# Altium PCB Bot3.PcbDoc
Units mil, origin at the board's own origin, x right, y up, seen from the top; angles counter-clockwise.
Board outline 1654.8 x 2956.3 mil, 2 copper layers (Top1, Bottom2), stack 42.17 mil thick; 83 components, 55 nets, 452 pads, 351 vias.
Unrouted connection lines stored in the file: 11.
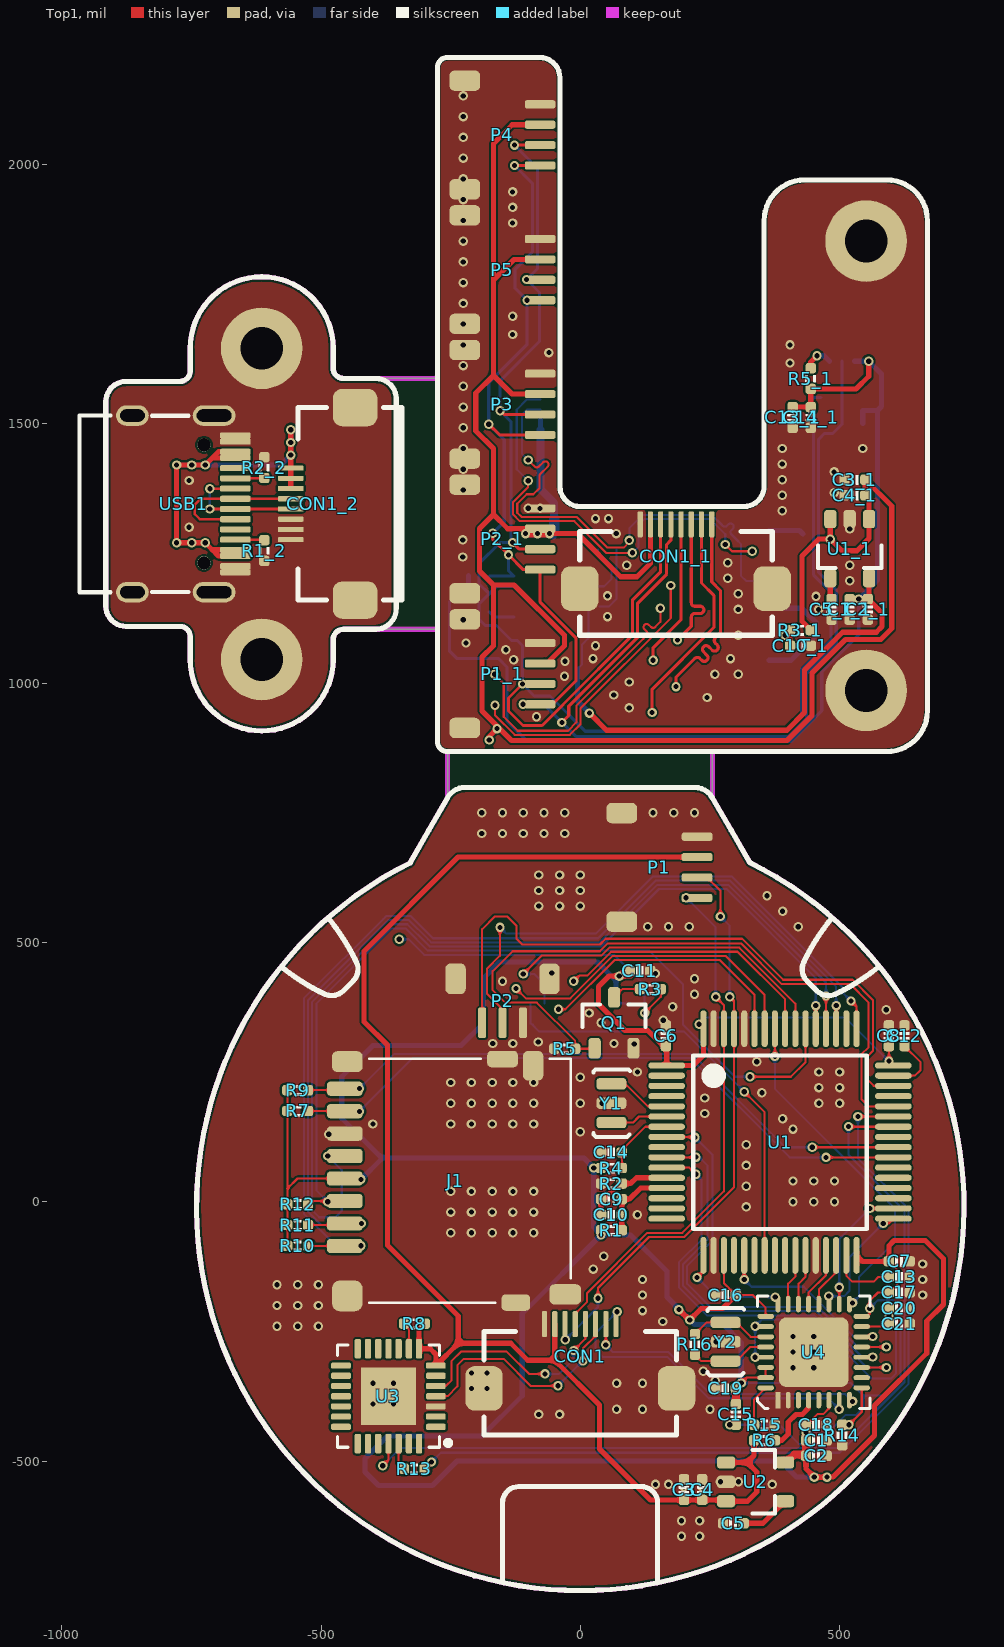
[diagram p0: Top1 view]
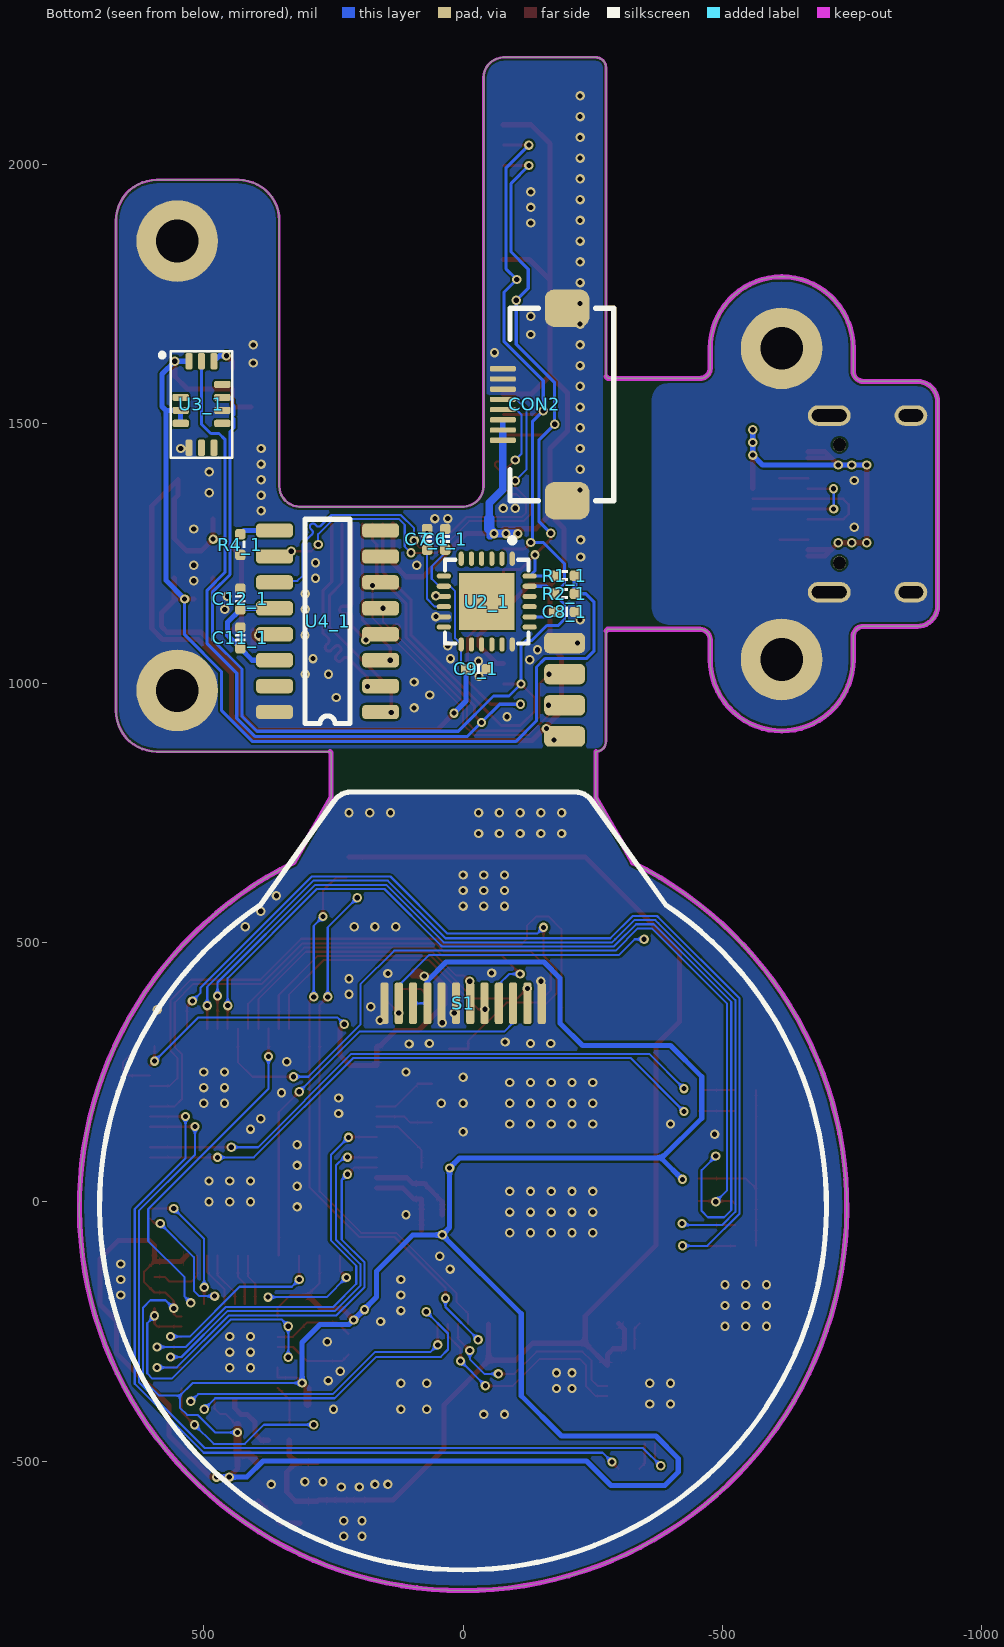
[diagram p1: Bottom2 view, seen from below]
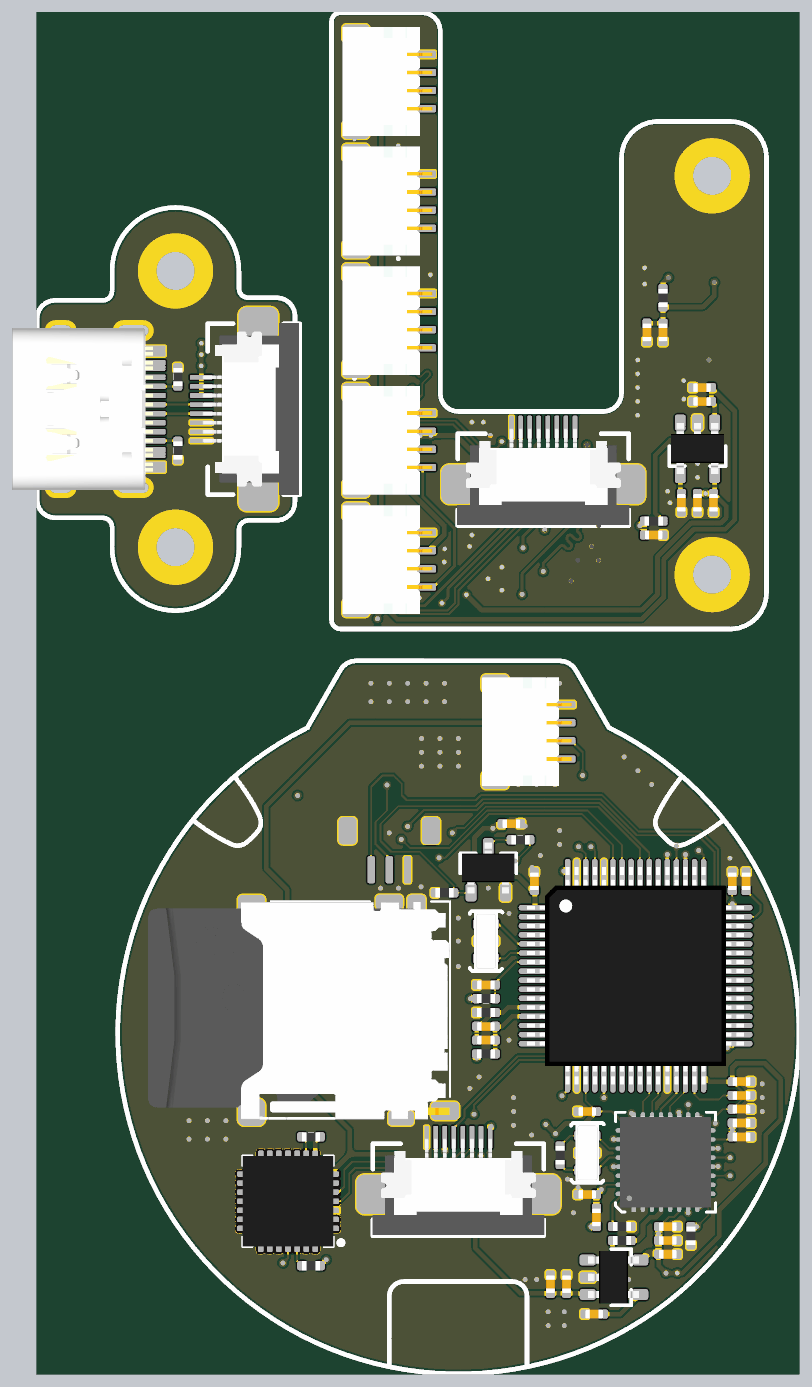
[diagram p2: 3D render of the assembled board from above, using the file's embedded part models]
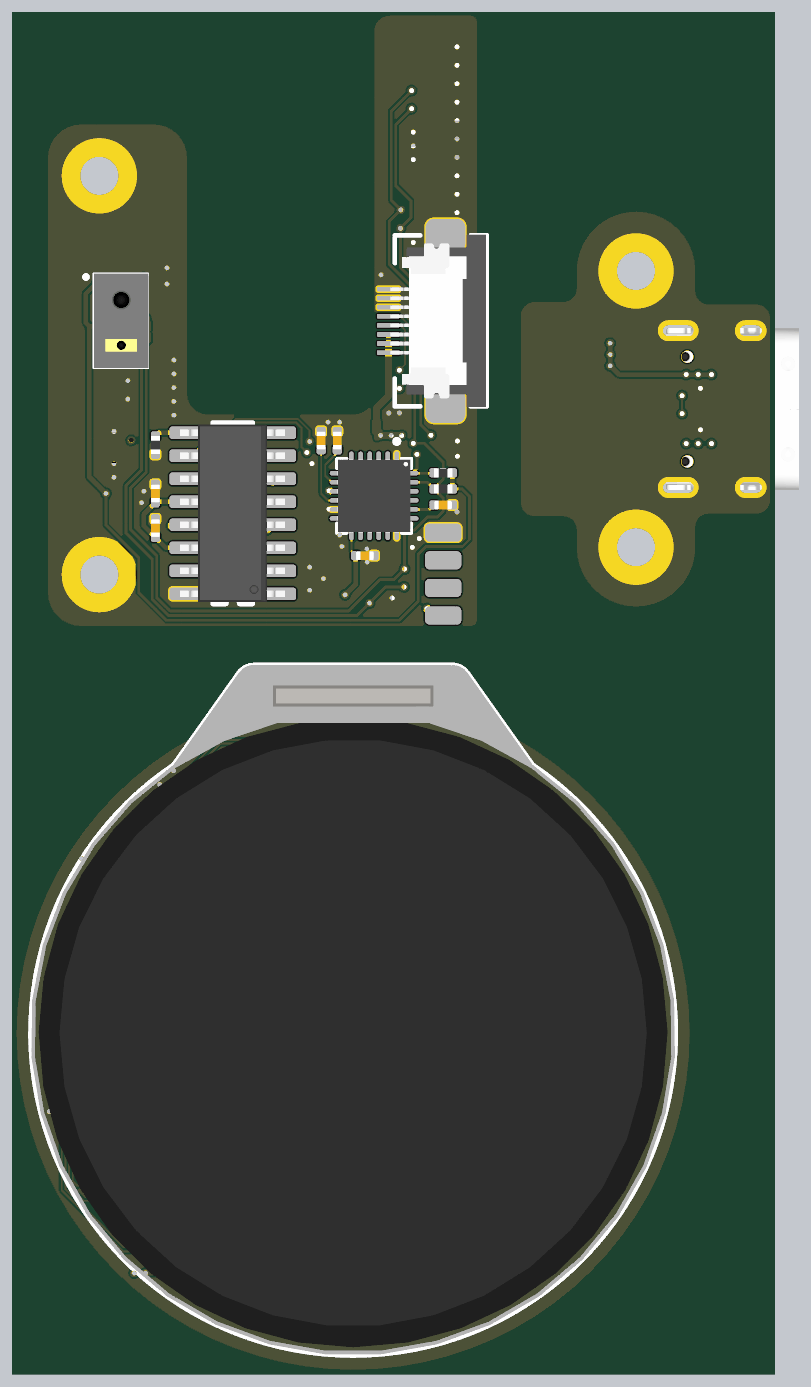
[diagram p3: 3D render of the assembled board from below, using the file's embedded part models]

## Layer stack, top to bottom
Top Solder: solder mask 0.4, Solder Resist, Dk 3.5
Top1: signal copper 1.4
Dielectric 1: prepreg 39.3701, PP-006, Dk 4.1
Bottom2: signal copper 1.4
Bottom Solder: solder mask 0.4, Solder Resist, Dk 3.5

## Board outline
-752.13,1045.51 -752.13,1089.61 ccw(c-771.81,1089.61) -771.81,1109.29 -875.58,1109.29 cw(c-875.58,1148.66) -914.95,1148.66 -914.95,1542.36 cw(c-875.58,1542.36) -875.58,1581.73 -771.81,1581.73 ccw(c-771.81,1601.42) -752.13,1601.42 -752.13,1645.51 cw(c-614.33,1645.51) -476.54,1645.51 -476.54,1607.05 ccw(c-456.85,1607.05) -456.85,1587.36 -279.64,1587.36 -275.59,1591.41 -275.59,2186.75 cw(c-255.91,2186.75) -255.91,2206.43 -78.74,2206.43 cw(c-78.74,2167.06) -39.37,2167.06 -39.37,1379.66 ccw(c0,1379.66) 0,1340.29 314.96,1340.29 ccw(c314.96,1379.66) 354.33,1379.66 354.33,1891.47 cw(c433.07,1891.47) 433.07,1970.21 590.55,1970.21 cw(c590.55,1891.47) 669.29,1891.47 669.29,946.59 cw(c590.55,946.59) 590.55,867.85 256.85,867.85 254.64,865.64 254.64,779.01 290.88,716.22 326.65,654.22 326.51,653.93 cw(c0,-10) -327.21,653.58 -327.58,654.33 -292.13,716.15 -256.03,779.09 -256.03,867.72 -255.91,867.85 cw(c-255.91,887.54) -275.59,887.54 -275.59,1100.59 -278.66,1103.66 -456.85,1103.66 ccw(c-456.85,1083.98) -476.54,1083.98 -476.54,1045.51 cw(c-614.33,1045.51)

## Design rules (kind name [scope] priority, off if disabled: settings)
Clearance Clearance_Logo [InNetClass('Logo')] p1: gap=8 ignorepadtopadclearanceinfootprint=FALSE
Clearance [All] p2: gap=4 ignorepadtopadclearanceinfootprint=FALSE except(0: Arc-Hole Track-Hole SMDPad-Hole THPad-Hole Via-Hole Fill-Hole Poly-Hole Region-Hole Text-Hole)
ComponentClearance [All] p1: gap=0 collisioncheckmode=3 verticalgap=0 showdistances=FALSE
DiffPairsRouting [All] p1: maxlimit=9 minlimit=9 mostfreqgap=9 toplayer_minwidth=15 toplayer_maxwidth=15 toplayer_prefwidth=15 bottomlayer_minwidth=15 bottomlayer_maxwidth=15 bottomlayer_prefwidth=15 maxuncoupledlength=500
FanoutControl Fanout_BGA [All] p1: bgadir=Out bgaviamode=Centered fanoutstyle=Auto fanoutdirection=Alternating viagrid=1 // Fanout_BGA (Default Rule)
HoleSize [All] p1: absolutevalues=TRUE maxlimit=10000 minlimit=8 maxpercent=80.000 minpercent=20.000
MinimumSolderMaskSliver [All] p1 off: minsoldermaskwidth=2
PlaneClearance [All] p1: clearance=8
PlaneConnect [All] p1: planeconnectstyle=Direct reliefexpansion=20 reliefentries=4 reliefconductorwidth=10 reliefairgap=10
PolygonConnect [All] p1: connectstyle=Direct reliefconductorwidth=10 reliefentries=4 polygonreliefangle="90 Angle" airgapwidth=10
RoutingVias [All] p1: holewidth=8 width=16 viastyle="Through Hole" minholewidth=6 minwidth=12 maxholewidth=28 maxwidth=50
SilkToSilkClearance [All] p1: silktosilkclearance=0
SilkToSolderMaskClearance [IsPad] p1: minsilkscreentomaskgap=0 clearancetoexposedcopper=TRUE
SolderMaskExpansion [All] p1: expansion=3 istentingtop=FALSE
Width Logo [InNetClass('Logo')] p1: maxlimit=100 minlimit=0.1 preferedwidth=10
Width GND [(InNet('AGND') OR InNet('GND'))] p2: maxlimit=50 minlimit=4 preferedwidth=10
Width VCC [(InNet('VDD_SYS_3.3V') OR InNet('VDD_AV_3.3V') OR InNet('VDD_5V') OR InNet('VDD1V2-SYS') OR InNet('VDD1V1-EPHY') OR InNet('VDD-CPUX') OR InNet('VDD-CPUS') OR InNet('VDD-CPUFB') OR InNet('VCC-DRAM'))] p3: maxlimit=50 minlimit=4 preferedwidth=10
Width [All] p4: maxlimit=10000 minlimit=4 preferedwidth=4
21 further rules are at their usual default settings.

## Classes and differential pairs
component class Main: C1 C2 C3 C4 C5 C6 C7 C8 C9 C10 C11 C12 C13 C14 C15 C16 C17 C18 C19 C20 C21 CON1 J1 P1 P2 Q1 R1 R2 R3 R4 R5 R6 R7 R8 R9 R10 R11 R12 R13 R14 R15 R16 S1 U1 U2 U3 U4 Y1 Y2

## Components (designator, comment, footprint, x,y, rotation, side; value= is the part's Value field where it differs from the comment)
C1 "0.1uF" CAP_0402 455,-460 r180 top value=0.1u
C1_1 "0.1uF" CAP_0402 519.41,1142.14 r90 top value=0.1u (schematic designator C1)
C2 "10uF" CAP_0402 455,-490 r180 top value=0.1u
C2_1 "10uF" CAP_0402 554.41,1142.14 r90 top value=0.1u (schematic designator C2)
C3 "10uF" CAP_0402 200,-555 r270 top value=0.1u
C3_1 "10uF" CAP_0402 529.41,1392.14 r0 top value=0.1u (schematic designator C3)
C4 "0.1uF" CAP_0402 235,-555 r270 top value=0.1u
C4_1 "0.1uF" CAP_0402 529.41,1362.14 r0 top value=0.1u (schematic designator C4)
C5 "10nF" CAP_0402 295,-620 r0 top value=0.1u
C5_1 "10nF" CAP_0402 484.41,1142.14 r90 top value=0.1u (schematic designator C5)
C6 "0.1uF" CAP_0402 165,320 r270 top value=0.1u
C6_1 "10nF" CAP_0402 34.41,1277.14 r90 bottom value=0.1u (schematic designator C6)
C7 "0.1uF" CAP_0402 615,-115 r180 top value=0.1u
C7_1 "0.1uF" CAP_0402 69.41,1277.14 r90 bottom value=0.1u (schematic designator C7)
C8 "0.1uF" CAP_0402 595,320 r270 top value=0.1u
C8_1 "2.2nF" CAP_0402 -195.59,1137.14 r0 bottom value=0.1u (schematic designator C8)
C9 "0.1uF" CAP_0402 60,5 r0 top value=0.1u
C9_1 "0.1uF" CAP_0402 -25.59,1027.14 r0 bottom value=0.1u (schematic designator C9)
C10 "10uF" CAP_0402 60,-25 r0 top value=0.1u
C10_1 "10uF" CAP_0402 424.41,1072.14 r180 top value=0.1u (schematic designator C10)
C11 "0.1uF" CAP_0402 115,445 r180 top value=0.1u
C11_1 "10uF" CAP_0402 429.41,1087.14 r90 bottom value=0.1u (schematic designator C11)
C12 "10uF" CAP_0402 625,320 r270 top value=0.1u
C12_1 "0.1uF" CAP_0402 429.41,1162.14 r90 bottom value=0.1u (schematic designator C12)
C13 "10uF" CAP_0402 615,-145 r180 top value=0.1u
C13_1 "10uF" CAP_0402 409.41,1512.14 r270 top value=0.1u (schematic designator C13)
C14 "0.1uF" CAP_0402 60,95 r0 top value=0.1u
C14_1 "0.1uF" CAP_0402 444.41,1512.14 r270 top value=0.1u (schematic designator C14)
C15 "10nF" CAP_0402 300,-410 r270 top value=0.1u
C16 "0.1uF" CAP_0402 280,-180 r180 top value=0.1u
C17 "0.1uF" CAP_0402 615,-175 r0 top value=0.1u
C18 "0.1uF" CAP_0402 455,-430 r0 top value=0.1u
C19 "0.1uF" CAP_0402 280,-360 r180 top value=0.1u
C20 "10uF" CAP_0402 615,-205 r0 top value=0.1u
C21 "0.1uF" CAP_0402 615,-235 r0 top value=0.1u
CON1 "FFC_0.5_8" FFC_0.5_8 0,-325 r0 top
CON1_1 "FFC_0.5_8" FFC_0.5_8 184.41,1217.14 r0 top (schematic designator CON1)
CON1_2 "FFC_0.5_8" FFC_0.5_8 -469.33,1345.51 r90 top locked (schematic designator CON1)
CON2 "FFC_0.5_8" FFC_0.5_8 -165.59,1537.14 r90 bottom locked
J1 "TF-Socket" "TF-Card-Amphenol with TF" -454.13,44.68 r270 top locked
P1 "SH1.0-4P" SH1.0-4P 225,644.69 r270 top locked
P1_1 "SH1.0-4P" SH1.0-4P -77.59,1018.17 r270 top locked (schematic designator P1)
P2 "SH1.0-3P-STAND" SH1.0-3P-STAND -150,345 r180 top locked
P2_1 "SH1.0-4P" SH1.0-4P -77.59,1277.85 r270 top locked (schematic designator P2)
P3 "SH1.0-4P" SH1.0-4P -77.59,1537.54 r270 top locked
P4 "SH1.0-4P" SH1.0-4P -77.59,2056.91 r270 top locked
P5 "SH1.0-4P" SH1.0-4P -77.59,1797.22 r270 top locked
Q1 "AO3400A" SOT23-3 65,345 r90 top locked
R1 "0R" RES_0402 60,-55 r180 top value=22R
R1_1 "10K" RES_0402 -195.59,1207.14 r180 bottom value=22R (schematic designator R1)
R1_2 "5.1K" RES_0402 -609.33,1255.51 r90 top value=22R (schematic designator R1)
R2 "0R" RES_0402 60,35 r180 top value=22R
R2_1 "10K" RES_0402 -195.59,1172.14 r180 bottom value=22R (schematic designator R2)
R2_2 "5.1K" RES_0402 -609.33,1415.51 r90 top value=22R (schematic designator R2)
R3 "10R" RES_0402 135,410 r0 top value=22R
R3_1 "4.7R" RES_0402 424.41,1102.14 r180 top value=22R (schematic designator R3)
R4 "10K" RES_0402 60,65 r180 top value=22R
R4_1 "100K" RES_0402 429.41,1267.14 r90 bottom value=22R (schematic designator R4)
R5 "10K" RES_0402 -30,295 r0 top value=22R
R5_1 "10K" RES_0402 444.41,1587.14 r90 top value=22R (schematic designator R5)
R6 "0R" RES_0402 355,-460 r0 top value=22R
R7 "47K" RES_0402 -545,175 r0 top value=22R
R8 "10K" RES_0402 -320,-235 r180 top value=22R
R9 "47K" RES_0402 -545,215 r0 top value=22R
R10 "47K" RES_0402 -545,-85 r0 top value=22R
R11 "47K" RES_0402 -545,-45 r0 top value=22R
R12 "47K" RES_0402 -545,-5 r0 top value=22R
R13 "200R" RES_0402 -320,-515 r180 top value=22R
R14 "10K" RES_0402 505,-450 r270 top value=22R
R15 "12K" RES_0402 355,-430 r0 top value=22R
R16 "1M" RES_0402 221,-275 r90 top value=22R
S1 "LCD-240x240-ROUND" LCD-240x240-ROUND 0,65 r0 bottom locked
U1 "STM32F405RGT6" LQFP-64_N 385,115 r0 top locked
U1_1 "LP2992 3V3" SOT23-5 519.41,1257.14 r270 top (schematic designator U1)
U2 "LP2992 3V3" SOT23-5 340,-540 r0 top
U2_1 "MPU6050" QFN-24 -45.59,1157.14 r270 bottom (schematic designator U2)
U3 "CP2102" QFN-28 -370,-375 r180 top value=Value
U3_1 "PAJ7620U2" PAJ7620U2 504.41,1537.14 r180 bottom locked (schematic designator U3)
U4 "USB3300-EZK-TR" QFN-32 450,-290 r90 top
U4_1 "HS8836A" SO-16N 266.41,1114.14 r0 bottom (schematic designator U4)
USB1 "Type-C" Type-C-TOP -764.33,1345.51 r180 top locked
Y1 "8MHz" 晶振-3P 60,190 r270 top
Y2 "24MHz" 晶振-3P 280,-270 r270 top

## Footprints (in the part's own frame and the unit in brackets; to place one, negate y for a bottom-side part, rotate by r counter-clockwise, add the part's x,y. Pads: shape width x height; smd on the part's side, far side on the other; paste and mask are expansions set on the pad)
CAP_0402 [mil]
  rrect50% 20x20 smd: 1(-20,0) 2(20,0)
  silkscreen extent -7,-9 7,9, body extent -20,-10 20,10, height 20
FFC_0.5_8 [mil]
  rrect50% 72x86 smd: 0(-185.63,-35) 0(185.63,-35)
  rrect50% 10x50 smd: 1(-68.9,89) 2(-49.21,89) 3(-29.53,89) 4(-9.84,89) 5(9.84,89) 6(29.53,89) 7(49.21,89) 8(68.9,89)
  silkscreen extent -186,-125 186,75, body extent -187,-124 187,87, height 82
LCD-240x240-ROUND [mm]
  rrect50% 0.4x2.032 smd: 1(3.85,-8.066) 2(3.15,-8.066) 3(2.45,-8.066) 4(1.75,-8.066) 5(1.05,-8.066) 6(0.35,-8.066) 7(-0.35,-8.066) 8(-1.05,-8.066) 9(-1.75,-8.066) 10(-2.45,-8.066) 11(-3.15,-8.066) 12(-3.85,-8.066)
  silkscreen extent -17.8,-18.41 17.8,19.69, body extent -17.8,-18.41 17.8,19.69
LQFP-64_N [mm] "Thin QFP, 64-Leads, Body 10x10mm, Pitch 0.5mm, IPC Medium Density"
  oval 1.8x0.3 smd: 1(-5.55,3.75) 2(-5.55,3.25) 3(-5.55,2.75) 4(-5.55,2.25) 5(-5.55,1.75) 6(-5.55,1.25) 7(-5.55,0.75) 8(-5.55,0.25) 9(-5.55,-0.25) 10(-5.55,-0.75) 11(-5.55,-1.25) 12(-5.55,-1.75) 13(-5.55,-2.25) 14(-5.55,-2.75) 15(-5.55,-3.25) 16(-5.55,-3.75) 33(5.55,-3.75) 34(5.55,-3.25) 35(5.55,-2.75) 36(5.55,-2.25) 37(5.55,-1.75) 38(5.55,-1.25) 39(5.55,-0.75) 40(5.55,-0.25) 41(5.55,0.25) 42(5.55,0.75) 43(5.55,1.25) 44(5.55,1.75) 45(5.55,2.25) 46(5.55,2.75) 47(5.55,3.25) 48(5.55,3.75)
  oval 0.3x1.8 smd: 17(-3.75,-5.55) 18(-3.25,-5.55) 19(-2.75,-5.55) 20(-2.25,-5.55) 21(-1.75,-5.55) 22(-1.25,-5.55) 23(-0.75,-5.55) 24(-0.25,-5.55) 25(0.25,-5.55) 26(0.75,-5.55) 27(1.25,-5.55) 28(1.75,-5.55) 29(2.25,-5.55) 30(2.75,-5.55) 31(3.25,-5.55) 32(3.75,-5.55) 49(3.75,5.55) 50(3.25,5.55) 51(2.75,5.55) 52(2.25,5.55) 53(1.75,5.55) 54(1.25,5.55) 55(0.75,5.55) 56(0.25,5.55) 57(-0.25,5.55) 58(-0.75,5.55) 59(-1.25,5.55) 60(-1.75,5.55) 61(-2.25,5.55) 62(-2.75,5.55) 63(-3.25,5.55) 64(-3.75,5.55)
  silkscreen extent -4.25,-4.25 4.25,4.25, body extent -5.99,-5.99 5.98,5.98, height 1.6
PAJ7620U2 [mm]
  rrect50% 0.35x0.8 smd: 1(-0.61,2.12) 2(0,2.12) 3(0.61,2.12) 8(0.61,-2.12) 9(0,-2.12) 10(-0.61,-2.12)
  rrect50% 0.8x0.35 smd: 4(1.02,0.983) 5(1.02,0.348) 6(1.02,-0.287) 7(1.02,-0.922) 11(-1.02,-0.922) 12(-1.02,-0.287) 13(-1.02,0.348)
  silkscreen extent -1.95,-2.6 1.5,2.6, body extent -1.48,-2.6 1.52,2.6, height 1.9
QFN-24 [mm] "QFN, 24-Leads, Body 4.1x4.1mm (max), Pitch 0.50mm, IPC Low Density"
  oval 0.7x0.25 smd: 1(-2.1,1.25) 2(-2.1,0.75) 3(-2.1,0.25) 4(-2.1,-0.25) 5(-2.1,-0.75) 6(-2.1,-1.25) 13(2.1,-1.25) 14(2.1,-0.75) 15(2.1,-0.25) 16(2.1,0.25) 17(2.1,0.75) 18(2.1,1.25)
  oval 0.25x0.7 smd: 7(-1.25,-2.1) 8(-0.75,-2.1) 9(-0.25,-2.1) 10(0.25,-2.1) 11(0.75,-2.1) 12(1.25,-2.1) 19(1.25,2.1) 20(0.75,2.1) 21(0.25,2.1) 22(-0.25,2.1) 23(-0.75,2.1) 24(-1.25,2.1)
  rect 2.8x2.7 smd: ""(0,0)
  silkscreen extent -3.12,-2.05 2.05,2.05, body extent -2.02,-2.02 2.02,2.02, height 0.95
QFN-28 [mil]
  rrect50% 38x12 smd mask+5: 1(-91.5,59.06) 2(-91.5,39.37) 3(-91.5,19.68) 4(-91.5,0) 5(-91.5,-19.68) 6(-91.5,-39.37) 7(-91.5,-59.06) 15(91.5,-59.06) 16(91.5,-39.37) 17(91.5,-19.68) 18(91.5,0) 19(91.5,19.68) 20(91.5,39.37) 21(91.5,59.06)
  rrect50% 12x38 smd mask+5: 8(-59.06,-91.5) 9(-39.37,-91.5) 10(-19.69,-91.5) 11(0,-91.5) 12(19.68,-91.5) 13(39.37,-91.5) 14(59.06,-91.5) 22(59.06,91.5) 23(39.37,91.5) 24(19.68,91.5) 25(0,91.5) 26(-19.69,91.5) 27(-39.37,91.5) 28(-59.06,91.5)
  rect 106.3x110.24 smd: 29(0,0)
  silkscreen extent -120,-99 99,99, body extent -99,-99 98,98, height 35
QFN-32 [mm]
  rect 0.81x0.239 smd paste+0 mask+0: 1(-2.351,1.75)
  rrect100% 0.81x0.239 smd paste+0 mask+0: 2(-2.351,1.25) 3(-2.351,0.75) 4(-2.351,0.25) 5(-2.351,-0.25) 6(-2.351,-0.75) 7(-2.351,-1.25) 8(-2.351,-1.75) 17(2.351,-1.75) 18(2.351,-1.25) 19(2.351,-0.75) 20(2.351,-0.25) 21(2.351,0.25) 22(2.351,0.75) 23(2.351,1.25) 24(2.351,1.75)
  rrect100% 0.239x0.81 smd paste+0 mask+0: 9(-1.75,-2.351) 10(-1.25,-2.351) 11(-0.75,-2.351) 12(-0.25,-2.351) 13(0.25,-2.351) 14(0.75,-2.351) 15(1.25,-2.351) 16(1.75,-2.351) 25(1.75,2.351) 26(1.25,2.351) 27(0.75,2.351) 28(0.25,2.351) 29(-0.25,2.351) 30(-0.75,2.351) 31(-1.25,2.351) 32(-1.75,2.351)
  rrect20% 3.4x3.4 smd paste-1000 mask+0: 33(0,0)
  silkscreen extent -2.76,-2.76 2.76,2.76, body extent -2.51,-2.51 2.51,2.51, height 0.85
RES_0402 [mil]
  rrect50% 20x20 smd: 1(-20,0) 2(20,0)
  silkscreen extent -7,-10 7,10, body extent -20,-10 20,10, height 14
SH1.0-3P-STAND [mm]
  rrect50% 0.4x1.5 smd: 1(-1,0) 2(0,0) 3(1,0)
  rrect50% 1x1.5 smd: SH1(-2.3,-2.15) SH2(2.3,-2.15)
  body extent -2.5,-2.91 2.5,0.69, height 4.25
SH1.0-4P [mm]
  rrect50% 0.4x1.5 smd: 1(-1.5,0) 2(-0.5,0) 3(0.5,0) 4(1.5,0)
  rrect50% 1x1.5 smd: SH1(-2.659,-3.683) SH2(2.659,-3.683)
  body extent -3,-4.42 3,0.54, height 3.14
SO-16N [mm]
  rrect50% 1.8x0.7 smd: 1(-2.723,4.318) 2(-2.723,3.048) 3(-2.723,1.778) 4(-2.723,0.508) 5(-2.723,-0.762) 6(-2.723,-2.032) 7(-2.723,-3.302) 8(-2.723,-4.572) 9(2.469,-4.572) 10(2.469,-3.302) 11(2.469,-2.032) 12(2.469,-0.762) 13(2.469,0.508) 14(2.469,1.778) 15(2.469,3.048) 16(2.469,4.318)
  silkscreen extent -1.23,-5.13 0.97,4.87, body extent -3,-5.03 2.8,4.77, height 1.75
SOT23-3 [mm] "SOT23, 3-Leads, Body 3.1x3.0mm (max), Pitch 0.95mm, IPC Medium Density"
  rrect50% 1x0.6 smd: 1(-1.246,0.95) 2(-1.246,-0.95) 3(1.246,0)
  silkscreen extent -0.2,-1.55 0.9,1.55, body extent -1.3,-1.45 1.5,1.45, height 1.2
SOT23-5 [mm] "SOT23, 3-Leads, Body 3.1x3.0mm (max), Pitch 0.95mm, IPC Medium Density"
  rrect50% 0.889x0.6 smd: 1(-1.5,0.95) 2(-1.5,0) 3(-1.5,-0.95) 4(1.396,-0.95) 5(1.396,0.95)
  silkscreen extent -0.2,-1.55 0.9,1.55, body extent -1.48,-1.45 1.32,1.45, height 1.2
"TF-Card-Amphenol with TF" [mm]
  rrect50% 0.7x1.75 smd: 1(3.3,0) 2(2.2,0) 3(1.1,0) 4(0,0) 5(-1.1,0) 6(-2.2,0) 7(-3.3,0) 8(-4.4,0)
  rrect50% 1x1.55 smd: 9(5.675,10.8)
  rrect50% 1.45x1 smd: 10(-5.525,9.225)
  rrect50% 1.5x1.5 smd: S1(5.75,0.125)
  rrect50% 1.016x1.5 smd: S2(-5.727,0.125)
  rrect50% 0.8x1.4 smd: S3(6.075,8.375)
  rrect50% 0.8x1.5 smd: S4(-5.85,7.725)
  silkscreen extent -5.87,1.19 6.07,11.07, body extent -5.85,-5.58 6.15,11.06, height 1.69
Type-C-TOP [mm]
  round 0.65 hole 0.65: 0(-0.98,2.89) 0(-0.98,-2.89)
  oval 1.6x1 hole 0.6 slot 1.2 at 0 deg: 1(2.52,4.325) 2(2.52,-4.325)
  oval 2.1x1 hole 0.6 slot 1.7 at 0 deg: 3(-1.48,-4.325) 4(-1.48,4.325)
  rrect50% 1.5x0.3 smd: A1(-2.52,-3.35) A4(-2.52,-2.55) A5(-2.52,-1.25) A6(-2.52,-0.25) A7(-2.52,0.25) A8(-2.52,1.25) A9(-2.52,2.55) A12(-2.52,3.35) B1(-2.52,3.05) B4(-2.52,2.25) B5(-2.52,1.75) B6(-2.52,0.75) B7(-2.52,-0.75) B8(-2.52,-1.75) B9(-2.52,-2.25) B12(-2.52,-3.05)
  silkscreen extent -0.22,-4.33 5.12,4.33, body extent -2.57,-4.48 5.18,4.48, height 3.26
晶振-3P [mm] "贴片晶振"
  rrect50% 0.55x1.45 smd: 1(-0.95,0) 2(0,0) 3(0.95,0)
  silkscreen extent -1.65,-0.89 1.65,0.91, body extent -1.6,-0.89 1.65,0.89, height 0.7

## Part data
C1 C1_1 C2 C2_1 C3 C3_1 C4 C4_1 C5 C5_1 C6 C6_1 C7 C7_1 C8 C8_1 C9 C9_1 C10 C10_1 C11 C11_1 C12 C12_1 C13 C13_1 C14 C14_1 C15 C16 C17 C18 C19 C20 C21: library part 电容-0402, "Capacitor"
CON1 CON1_1 CON1_2 CON2: "FFC"
J1: "10 _8 + 2_ Position Card Connector Secure Digital - microSDâ„¢ Surface Mount, Right Angle Gold", Package=None
P2: "Header"
Q1: "N-MOS"
R1 R1_1 R1_2 R2 R2_1 R2_2 R3 R3_1 R4 R4_1 R5 R5_1 R6 R7 R8 R9 R10 R11 R12 R13 R14 R15 R16: library part 电阻-0402, "Resistor"
S1: "显示屏"
U1: "ARM Cortex-M4 32-bit MCU+FPU, 210 DMIPS, 1024 kB Flash, 192 kB Internal RAM, 51 I/Os, 64-pin LQFP, -40 to 85 degC, Tray", I/Os (High Current)=51, Manufacturer=STMicroelectronics, Operating Frequency(F) (Processor speed) (MHz)=168, Supplier Part Number 1=497-11767-ND, Supply Voltage(Vcc) max (V)=3.6, Supply Voltage(Vcc) min (V)=1.8
U1_1 U2: library part LP2992, "LDO"
U2_1: "六轴传感器"
U3: "USB转TTL"
U3_1: "module sensorPAJ7620U2 : 54/TRAY, 5400/BOX, 32400/CARTON", Package=None
U4_1: "USB2.0 HUB"
USB1: library part USB-Type-C-TOP
Y1 Y2: library part 晶振-3Pin, "村田贴片"

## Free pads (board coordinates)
  round 157.48 hole 82.68: ""(-614.33,1045.51) ""(-614.33,1645.51) ""(551.18,985.96) ""(551.18,1852.1)
  rrect50% 78.74x39.37 smd far side: ""(-195.59,897.14) ""(-195.59,957.14) ""(-195.59,1017.14) ""(-195.59,1077.14)

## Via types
v1: diameter 18, hole 10, Top1 to Bottom2, tented both sides, 351 vias

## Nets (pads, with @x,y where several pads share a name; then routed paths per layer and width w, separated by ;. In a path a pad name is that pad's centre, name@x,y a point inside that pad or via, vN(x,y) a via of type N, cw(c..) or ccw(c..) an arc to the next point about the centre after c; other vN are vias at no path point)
AGND: C9.1 C10.1 R2.1 U1.12 | length 170.6
  Top1 w10: C10.1 40,0 75,35 R2.1 97,35 108.1,46.1 U1.12
AVCC: C9.2 C10.2 R1.1 U1.13 | length 155.4
  Top1 w10: R1.1 C10.2 C9.2 95,5 116.42,26.42 U1.13
GND: C1.1 C2.1 C3.1 C4.1 C5.1 C6.1 C7.1 C8.1 C11.1 C12.1 C13.1 C14.1 C16.2 C17.2 C18.2 C19.2 C20.2 C21.2 CON1.0 CON1.1 J1.6 J1.9 J1.10 J1.S1 J1.S2 J1.S3 J1.S4 P1.1 P1.SH1 P1.SH2 P2.1 P2.SH1 P2.SH2 Q1.2 R2.2 R5.1 R14.2 R15.2 S1.1 S1.5 S1.6 S1.12 U1.18 U1.28 U1.60 U1.63 U2.2 U3.3 U3.29 U4.1 U4.2 U4.33 Y1.2 Y2.2
  other v1: 195,-645 230,-645 195,-615 230,-615 200,-550 235,-550 145,-545 170,-545 370,-545 270,-540 305,-540 -80,-410 -40,-410 70,-400 120,-400 250,-400 -400,-390 -360,-390 -210,-360 -180,-360 -400,-350 -360,-350 70,-350 120,-350 260,-345 -210,-330 -180,-330 237,-327 410,-320 450,-320 410,-290 450,-290 262,-270 410,-260 450,-260 -585,-240 -545,-240 -505,-240 159,-231 120,-210 -585,-200 -545,-200 -505,-200 120,-180 660,-180 -585,-160 -545,-160 -505,-160 120,-150 660,-150 25,-130 660,-120 45,-105 -250,-60 -210,-60 -170,-60 -130,-60 -90,-60 110,-25 -250,-20 -210,-20 -170,-20 -130,-20 -90,-20 320,-10 410,0 450,0 490,0 -250,20 -210,20 -170,20 -130,20 -90,20 320,30 410,40 450,40 490,40 320,70 320,110 -485,130 0,135 410,140 -400,150 -250,150 -210,150 -170,150 -130,150 -90,150 390,160 240,170 -250,190 -210,190 -170,190 -130,190 -90,190 0,190 42,190 460,190 500,190 240,200 350,210 460,220 500,220 -250,230 -210,230 -170,230 -130,230 -90,230 0,240 110,250 460,250 500,250 340,270 104,304 -169,305 -130,305 65,305 -81,308 40,345 160,350 17,364 590,370 178,376 220,400 -150,425 220,430 145,440 -55,441 130,530 170,530 210,530 420,530 390,560 -80,570 -40,570 0,570 360,590 -80,600 -40,600 0,600 -80,630 -40,630 0,630 -190,710 -150,710 -110,710 -70,710 -30,710 -190,750 -150,750 -110,750 -70,750 -30,750 140,750 180,750 220,750
I2C_SCL_1: CON1.3 P1.3 U1.61 | length 1106.7
  Top1 w4: v1(34,-186) 34,-166.31 132.31,-68 200,-68 296.42,28.42 U1.61 296.42,386.58 v1(288,395) ; P1.3 245,625 270,600 v1(270,550)
  Bottom2 w4: v1(-29,-266) 34,-203 v1(34,-186) ; v1(270,550) 288,532 v1(288,395)
I2C_SDA_1: CON1.4 P1.4 U1.62 | length 1010.5
  Top1 w4: CON1.4 -9.84,-215.84 13,-193 13,-176 129,-60 196.69,-60 276.73,20.05 276.73,379.27 v1(261,395)
  Bottom2 w4: v1(204,586) 261,529 v1(261,395)
LCD_BL_1: Q1.1 R5.2 U1.44 | length 1341.3
  Top1 w4: Q1.1@26.65,295 R5.2 -10,310 -84,384 -145,384 -169,408 -169,444.54 -130.54,483 37.75,483 52.75,498 309.69,498 387.69,420 520,420 556,384 556,298.18 542,284.18 542,198 556.1,183.9 U1.44
LCD_CS_1: S1.8 U1.59 | length 510.5
  Top1 w4: v1(-42,371) -29,371 66,466 269,466 335.79,399.21 U1.59
LCD_DC_1: S1.7 U1.56 | length 526.2
  Top1 w4: v1(-13,425) -2,436 13.37,436 59.37,482 303.06,482 394.84,390.22 U1.56
LCD_LEDK_1: R3.2 S1.2 | length 603.2
  Top1 w4: v1(124,364) 155,395 R3.2
  Bottom2 w4: v1(-349,506) -331,506 -301,476 65,476 124.02,416.98 S1.2
LCD_RST_1: S1.11 U1.58 | length 617.6
  Top1 w4: v1(-124,411) -105,392 -19.31,392 62.69,474 280,474 355.47,398.53 U1.58
LCD_SCL_1: S1.9 U1.55 | length 724.7
  Top1 w4: v1(-110,439) -74,475 41.06,475 56.06,490 306.37,490 414.53,381.85 U1.55
  Bottom2 w4: v1(-110,439) -88.83,439 -68.9,419.06 S1.9
LCD_SDA_1: S1.10 U1.23 | length 836.7
  Top1 w4: v1(316,212) 355.47,172.53 U1.23
  Bottom2 w4: S1.10 -96.46,345.46 -79,328 200,328 v1(316,212)
NetC5_2: C5.2 U2.4 | length 97.6
  Top1 w10: C5.2 352.35,-620 U2.4
NetC12_2: C12.2 U1.47 | length 115.9
  Top1 w4: U1.47 644.95,242.95 656,254 656,269 C12.2
NetC13_2: C13.2 U1.31 | length 129.8
  Top1 w4: U1.31 512.95,-142.95 524,-154 566,-154 575,-145 C13.2
NetC14_2: C14.2 R4.1 U1.7 | length 139.4
  Top1 w4: R4.1 C14.2 80,99 125.53,144.53 U1.7
NetC15_2: C15.2 R14.1 U4.9 | length 341.9
  Top1 w4: v1(518,-430) 542.57,-405.43 U4.9
  Bottom2 w4: v1(288,-430) 384,-430 421,-467 481,-467 v1(518,-430)
NetC20_1: C20.1 C21.1 U4.15 U4.26 U4.29 | length 590.4
  Top1 w4: U4.15 589.21,-240.79 C21.1 v1(595,-220) C20.1
  Bottom2 w4: v1(337,-300) v1(337,-240) 350,-227 448,-227 562,-341 599,-341 609,-331 609,-234 v1(595,-220)
NetQ1_3: Q1.3 R3.1 | length 56.6
  Top1 w4: Q1.3 80.94,410 R3.1
NetR6_2: R6.2 U4.4 | length 119.7
  Top1 w10: R6.2 389,-460 401,-448 401,-425 416,-410 428,-410 440.16,-397.84 U4.4
NetR8_2: R8.2 U3.9 | length 52.4
  Top1 w4: R8.2 -330.63,-244.37 U3.9
NetR13_2: R13.2 U3.26 | length 52.8
  Top1 w4: U3.26 -350.31,-504.68 R13.2
NetR15_1: R15.1 U4.32 | length 80.4
  Top1 w4: R15.1 335,-381.33 U4.32
NetR16_1: R16.1 U4.28 Y2.3 | length 152.9
  Top1 w4: R16.1 233.4,-307.4 Y2.3 300.6,-307.4 327.84,-280.16 U4.28
NetR16_2: R16.2 U4.27 Y2.1 | length 157.3
  Top1 w4: R16.2 243.4,-232.6 Y2.1 300.6,-232.6 328.47,-260.47 U4.27
NetU1_5: U1.5 Y1.1 | length 124.5
  Top1 w4: Y1.1 86.6,227.4 130.1,183.9 U1.5
NetU1_6: U1.6 Y1.3 | length 111.3
  Top1 w4: Y1.3 101.6,152.6 113.21,164.21 U1.6
SD_CLK_1: J1.5 U1.53 | length 1852
  Top1 w4: U1.53 v1(453.9,378.1)
  Bottom2 w4: v1(-487,88) -460,61 -460,-18 -472,-30 -503.37,-30 -517,-16.37 -517,385.31 -367.31,535 -333.69,535 -296.69,498 -290.69,492 40.63,492 46.63,498 151.63,603 282,603 453.9,431.1 v1(453.9,378.1)
SD_CMD_1: J1.3 R12.2 U1.54 | length 1707.8
  Top1 w4: R12.2 -518.62,1.38 J1.3 ; v1(327,241) 406,241 434.21,269.21 U1.54
  Bottom2 w4: v1(-487,0) -509,22 -509,382 -364,527 -337,527 -294,484 133,484 198,419 198,341.31 298.31,241 v1(327,241)
SD_D0_1: J1.7 R7.2 U1.39 | length 1222
  Top1 w4: R7.2 J1.7@-454.53,175 ; v1(473.53,85.47) U1.39
  Bottom2 w4: v1(-426,174) -323,277 212,277 403.53,85.47 v1(473.53,85.47)
SD_D1_1: J1.8 R9.2 U1.40 | length 1199.8
  Top1 w4: R9.2 J1.8@-457.05,215 ; v1(447,105) 603.35,105 U1.40
  Bottom2 w4: v1(-426,218) -359,285 215.31,285 395.31,105 v1(447,105)
SD_D2_1: J1.1 R10.2 U1.51 | length 1942.8
  Top1 w4: R10.2@-524.76,-85.24 J1.1 ; U1.51 v1(493.27,378.1)
  Bottom2 w4: v1(-423,-85) -471,-85 -533,-23 -533,391.94 -379.94,545 -373.94,551 -327.06,551 -284.06,508 34,508 145,619 288.63,619 493.27,414.36 v1(493.27,378.1)
SD_D3_1: J1.2 R11.2 U1.52 | length 1884.4
  Top1 w4: R11.2 J1.2@-457.2,-45 ; U1.52 v1(473.58,396.58)
  Bottom2 w4: v1(-422,-42) -425,-45 -499.69,-45 -525,-19.69 -525,388.63 -376.63,537 -370.63,543 -330.37,543 -293.37,506 -287.37,500 37.31,500 148.31,611 285.31,611 473.58,422.73 v1(473.58,396.58)
SWCLK_1: P2.2 U1.49 | length 1097.5
  Top1 w4: v1(-155,529) -155,474 -180,449 -180,401.03 -150,371.03 P2.2 ; v1(522,387) 532.64,376.36 U1.49
  Bottom2 w4: v1(-155,529) -143,517 30,517 140,627 292,627 506,413 506,403 v1(522,387)
SWDIO_1: P2.3 U1.46 | length 1249.5
  Top1 w4: P2.3 -189.37,525.63 -165,550 -141,550 -123,532 -123,507 -112,496 38,496 49,507 312,507 391,428 525,428 564,389 564,290.51 551,277.51 551,238 565.73,223.27 U1.46
UART_RX_1: R13.1 U1.43 | length 1624.9
  Top1 w4: R13.1 v1(-287,-502) ; v1(535.21,164.21) U1.43
  Bottom2 w4: v1(-287,-502) -269,-484 500,-484 633,-351 633,-14 535.21,83.79 v1(535.21,164.21)
UART_TX_1: U1.42 U3.25 | length 1744
  Top1 w4: v1(-381,-509) -370,-498 U3.25 ; v1(517,145) 517.47,144.53 U1.42
  Bottom2 w4: v1(-381,-509) -347,-475 497.69,-475 625,-347.69 625,-17.31 517,90.69 v1(517,145)
USB_CLK_1: U1.21 U4.14 | length 360.9
  Top1 w4: v1@316.1,-149.9 U1.21 ; U4.14 v1@563.53,-260.47
  Bottom2 w4: v1(316,-150) 330,-164 431,-164 527,-260 v1(564,-260)
USB_DATA0_1: U1.17 U4.24 | length 214.4
  Top1 w4: v1(225,-146) 237.36,-133.64 U1.17
  Bottom2 w4: v1(225,-146) 263,-184 v1(376,-184)
USB_DATA1_1: U1.26 U4.23 | length 99.6
  Top1 w4: U4.23 400.79,-158.21 414.53,-144.47 U1.26
USB_DATA2_1: U1.27 U4.22 | length 99.6
  Top1 w4: U4.22 421,-196.9 421,-158 434.21,-144.79 U1.27
USB_DATA3_1: U1.29 U4.21 | length 107.8
  Top1 w4: U4.21 440.16,-174.84 473.58,-141.42 U1.29
USB_DATA4_1: U1.30 U4.20 | length 107.8
  Top1 w4: U4.20 459.84,-169.16 493.27,-135.73 U1.30
USB_DATA5_1: U1.33 U4.19 | length 224.4
  Top1 w4: v1(584,-42) 594.14,-42 U1.33
  Bottom2 w4: v1(479,-182) 509,-182 519,-172 519,-107 v1(584,-42)
USB_DATA6_1: U1.34 U4.18 | length 254.3
  Top1 w4: U4.18 v1(499.21,-165.21) ; v1(558,-13) v1(558,-13) U1.34
  Bottom2 w4: v1(499.21,-165.21) 499.21,-71.79 v1(558,-13)
USB_DATA7_1: U1.57 U4.17 | length 658.5
  Top1 w4: v1(375.16,279.84) U1.57
  Bottom2 w4: v1(375.16,279.84) 375.16,217.84 607,-14 607,-76 537,-146 537,-183 v1(525,-195)
USB_DIR_1: U1.10 U4.12 | length 779.7
  Top1 w4: U1.10 v1@222.47,85.47 ; U4.12 v1@563.53,-299.84
  Bottom2 w4: v1(223,86) 229,86 245,70 245,-73.31 198,-120.31 198,-161.69 247.31,-211 454.63,-211 543,-299.37 v1(564,-299.37)
USB_DM_CP_1: CON1.5 U3.5 | length 421.5
  Top1 w4: U3.5 -259.31,-355.32 -248,-344 -248,-307 -230,-289 -142,-289 -99,-332 v1(-68,-332) ; v1(-13,-287) 9.84,-264.16 CON1.5
  Bottom2 w4: v1(-68,-332) -41,-332 -13,-304 v1(-13,-287)
USB_DM_ST_1: CON1.7 U4.8 | length 560.9
  Top1 w4: v1@49.21,-275.79 CON1.7
  Bottom2 w4: v1(49,-276) 63,-290 170,-290 251,-371 511,-371 v1(525,-385)
USB_DP_CP_1: CON1.6 U3.4 | length 459.9
  Top1 w4: U3.4 -256,-375 -237,-356 -237,-315 -225,-303 -148,-303 -96,-355 v1(-43,-355) ; v1(5,-307) 5,-283 29.53,-258.47 CON1.6
  Bottom2 w4: v1(-43,-355) v1(5,-307)
USB_DP_ST_1: CON1.8 U4.7 | length 608
  Bottom2 w4: v1(71,-212) 29,-254 29,-285 43,-299 167.69,-299 247.69,-379 478,-379 v1(499,-400)
USB_NXT_1: U1.11 U4.11 | length 814.3
  Top1 w4: U1.11 210.21,65.79 v1(223,53) ; U4.11 v1(590.16,-319.53)
  Bottom2 w4: v1(223,53) 234,42 234,-73 190,-117 190,-165 244,-219 451.31,-219 551.84,-319.53 v1(590.16,-319.53)
USB_STP_1: U1.8 U4.13 | length 852.6
  Top1 w4: U1.8 v1@220.16,124.84 ; U4.13 v1(590.16,-280.16)
  Bottom2 w4: v1(221,124) 255,90 255,-74.63 206,-123.63 206,-158.37 250.63,-203 457.94,-203 535.1,-280.16 v1(590.16,-280.16)
VBUS_IN: C3.2 C4.2 CON1.2 P1.2 R6.1 R8.1 U2.1 U2.3 U3.7 U3.8 | length 2697.8
  Top1 w10: R8.1 -310.94,-245.94 U3.8 -289.5,-283.5 -278.5,-294.5 U3.7 -235.56,-273 ; CON1.2 -49.21,-305.79 ; P1.2@220,664.37 -235.63,664.37 -417,483 -417,347 -372,302 -372,-84 -235.56,-220.44 -235.56,-273 ; U2.1 321.6,-502.6 ; R6.1 335,-489.2 321.6,-502.6 ; -235.56,-273 -134,-273 -101.21,-305.79 -49.21,-305.79 ; -49.21,-305.79 37,-392 37,-477 135,-575 C3.2 C4.2 278.54,-575 U2.3 322.6,-577.4 340,-560 340,-521 321.6,-502.6
VCC_3V3: C1.2 C2.2 C6.2 C7.2 C8.2 C11.2 C15.1 C16.1 C17.1 C18.1 C19.1 J1.4 R1.2 R4.2 R7.1 R9.1 R10.1 R11.1 R12.1 S1.3 S1.4 U1.1 U1.19 U1.32 U1.48 U1.64 U2.5 U4.6 U4.16 U4.25 U4.30 U4.31 | length 7300.8
  Top1 w4: R10.1 R11.1 R12.1 -565,25 ; R9.1 R7.1 -565,25 ; J1.4 -545.31,44.68 -565,25 ; U1.19 276.73,-156.73 C16.1 333,-180 357.43,-204.43 U4.25 ; C19.1 v1(310.39,-349.61) 320.79,-339.21 U4.31 U4.30 ; C18.1 437,-430 458,-409 469,-409 479.53,-398.47 U4.6 ; U4.16 552.9,-221.1 558,-216 v1(558,-205.67) 558,-191 574,-175 C17.1 615,-155 615,-135 C7.2 ; C8.2 v1(595,271.14) U1.48
  Top1 w10: C11.2 85,445 v1(75,435) ; C11.2@97.73,435 v1(75,435) ; v1(190,-208) 210,-228 v1(211,-228) 233,-206 274,-206 C16.1 ; U1.64 237.36,282.36 217.64,262.64 U1.1 166.5,298.5 C6.2 160,300 130,330 86,330 35,381 35,415 55,435 v1(75,435) ; C2.2 435,-515 v1(451,-531) v1(475.5,-531) 487,-531 567,-451 567,-393 668,-292 668,-230 700,-198 700,-110 665,-75 605,-75 595,-85 C7.2 544.13,-115 U1.32
  Top1 w15: C15.1 C19.1 ; U2.5@400,-500 412.4,-487.6 432.6,-487.6 C2.2 C1.2 v1(435,-445) C18.1
  Bottom2 w4: S1.4 S1.3 ; v1(229,342) 242,355 511.14,355 v1(595,271.14) ; v1(310.39,-349.61) 521.61,-349.61 546,-374 ; v1(435,-445) 478,-445 512,-411 532,-411 546,-397 546,-374 ; v1(558,-205.67) 573.67,-190 603,-190 617,-204 617,-343 586,-374 546,-374
  Bottom2 w10: v1(-423,43) -383,83 -383,84 ; S1.4 68.9,426.1 33,462 -156,462 -187,431 -187,344 -230,301 -400,301 -460,241 -460,161 -383,84 ; v1(310.39,-349.61) 310.39,-271.39 276,-237 220,-237 v1(211,-228) 167,-184 167,-134 97,-64 v1(40,-64) ; v1(475.5,-531) v1(451,-531) 417,-531 386,-500 -238,-500 -285,-547 -389,-547 -415,-521 -415,-495 -372,-452 -190,-452 -112,-374 -112,-216 v1(40,-64) ; -383,84 7,84 v1(26,65) 26,-50 v1(40,-64)
pads on no net: C1_1.1 C1_1.2 C2_1.1 C2_1.2 C3_1.1 C3_1.2 C4_1.1 C4_1.2 C5_1.1 C5_1.2 C6_1.1 C6_1.2 C7_1.1 C7_1.2 C8_1.1 C8_1.2 C9_1.1 C9_1.2 C10_1.1 C10_1.2 C11_1.1 C11_1.2 C12_1.1 C12_1.2 C13_1.1 C13_1.2 C14_1.1 C14_1.2 CON1_1.0 CON1_1.1 CON1_1.2 CON1_1.3 CON1_1.4 CON1_1.5 CON1_1.6 CON1_1.7 CON1_1.8 CON1_2.0 CON1_2.1 CON1_2.2 CON1_2.3 CON1_2.4 CON1_2.5 CON1_2.6 CON1_2.7 CON1_2.8 CON2.0 CON2.1 CON2.2 CON2.3 CON2.4 CON2.5 CON2.6 CON2.7 CON2.8 P1_1.1 P1_1.2 P1_1.3 P1_1.4 P1_1.SH1 P1_1.SH2 P2_1.1 P2_1.2 P2_1.3 P2_1.4 P2_1.SH1 P2_1.SH2 P3.1 P3.2 P3.3 P3.4 P3.SH1 P3.SH2 P4.1 P4.2 P4.3 P4.4 P4.SH1 P4.SH2 P5.1 P5.2 P5.3 P5.4 P5.SH1 P5.SH2 R1_1.1 R1_1.2 R1_2.1 R1_2.2 R2_1.1 R2_1.2 R2_2.1 R2_2.2 R3_1.1 R3_1.2 R4_1.1 R4_1.2 R5_1.1 R5_1.2 U1.2 U1.3 U1.4 U1.9 U1.14 U1.15 U1.16 U1.20 U1.22 U1.24 U1.25 U1.35 U1.36 U1.37 U1.38 U1.41 U1.45 U1.50 U1_1.1 U1_1.2 U1_1.3 U1_1.4 U1_1.5 U2_1. U2_1.1 U2_1.2 U2_1.3 U2_1.4 U2_1.5 U2_1.6 U2_1.7 U2_1.8 U2_1.9 U2_1.10 U2_1.11 U2_1.12 U2_1.13 U2_1.14 U2_1.15 U2_1.16 U2_1.17 U2_1.18 U2_1.19 U2_1.20 U2_1.21 U2_1.22 U2_1.23 U2_1.24 U3.1 U3.2 U3.6 U3.10 U3.11 U3.12 U3.13 U3.14 U3.15 U3.16 U3.17 U3.18 U3.19 U3.20 U3.21 U3.22 U3.23 U3.24 U3.27 U3.28 U3_1.1 U3_1.2 U3_1.3 U3_1.4 U3_1.5 U3_1.6 U3_1.7 U3_1.8 U3_1.9 U3_1.10 U3_1.11 U3_1.12 U3_1.13 U4.3 U4.5 U4.10 U4_1.1 U4_1.2 U4_1.3 U4_1.4 U4_1.5 U4_1.6 U4_1.7 U4_1.8 U4_1.9 U4_1.10 U4_1.11 U4_1.12 U4_1.13 U4_1.14 U4_1.15 U4_1.16 USB1.0 USB1.1 USB1.2 USB1.3 USB1.4 USB1.A1 USB1.A4 USB1.A5 USB1.A6 USB1.A7 USB1.A8 USB1.A9 USB1.A12 USB1.B1 USB1.B4 USB1.B5 USB1.B6 USB1.B7 USB1.B8 USB1.B9 USB1.B12
copper on no net: | length 20769
  Top1 w4: v1(-165.59,1017.14) -147.59,999.14 -147.59,935.14 -120.59,908.14 -23.59,908.14 -7.59,924.14 -7.59,956.14 121.41,1085.14 127.54,1091.27 ccw(c123.3,1095.51) 127.54,1099.76 123.65,1103.64 cw(c127.89,1107.89) 123.65,1112.13 cw(c127.89,1107.89) 132.14,1112.13 136.02,1108.24 ccw(c140.27,1112.48) 144.51,1108.24 154.41,1118.14 v1(154.41,1144.14) ; v1(-164.59,957.14) -164.59,938.14 -126.59,900.14 -20.28,900.14 0.41,920.83 0.41,951.14 174.41,1125.14 v1(174.41,1188.14) ; v1(-100.59,1390.14) -100.59,1378.14 -129.59,1349.14 -129.59,1325.14 -116.59,1312.14 -11.59,1312.14 49.41,1251.14 v1(100.41,1251.14) ; v1(-100.59,1430.14) -89.59,1419.14 -88.18,1417.73 ccw(c-83.93,1421.97) -79.69,1417.73 -71.55,1425.87 cw(c-67.3,1421.63) -63.06,1425.87 cw(c-67.3,1421.63) -63.06,1417.39 -76.83,1403.61 ccw(c-72.59,1399.37) -78.59,1399.37 -78.59,1380.14 -78.59,1376.14 -90.59,1364.14 -103.28,1364.14 -121.59,1345.83 -121.59,1328.46 -113.28,1320.14 -6.59,1320.14 52.41,1261.14 83.41,1261.14 94.41,1272.14 v1(94.41,1275.14) ; v1(279.41,1267.14) 292.41,1254.14 v1(331.41,1254.14)
  Top1 w5: v1(-714.49,1335.67) -665.12,1335.67 -558.33,1335.67 ; v1(-714.33,1374.51) -713.8,1375.04 -665.12,1375.04 ; -665.12,1276.61 -610.43,1276.61 ; -665.12,1315.98 -733.8,1315.98 -743.33,1325.51 -743.33,1344.51 -732.49,1355.35 -665.12,1355.35 -558.33,1355.35 ; -665.12,1394.72 -610.12,1394.72
  Top1 w6: v1(-176.59,1499.14) -155.93,1478.48 -77.59,1478.48 ; v1(-169.01,1288.72) -169.01,1277.57 v1(-138.59,1247.14) -110.24,1218.8 -77.59,1218.8 -77.59,1156.11 -8.59,1087.11 -8.59,1004.14 -53.62,959.11 -77.59,959.11 v1(-110.59,959.14) ; v1(-154.59,1525.14) -147.3,1517.85 -77.59,1517.85 ; v1(-130.59,1271.14) -117.61,1258.17 -77.59,1258.17 ; v1(-126.88,1997.85) -77.59,1997.85 ; v1(-126.88,2037.22) -77.59,2037.22 ; -77.59,998.48 -111.25,998.48 v1(-111.59,998.14) -138.59,971.14 -138.59,946.18 -110.55,918.14 -73.56,918.14 -32.32,959.39 -32.32,959.56 100.27,1092.14 100.27,1160 154.88,1214.61 154.88,1306.14 ; v1(-35.59,924.14) -22.32,937.41 -22.32,955.41 110.41,1088.14 110.41,1154.14 166.41,1210.14 166.41,1267.14 174.57,1275.3 174.57,1306.14 ; v1(138.41,943.14) 138.41,988.14 257.41,1107.14 257.41,1169.14 233.62,1192.93 233.62,1306.14 ; v1(140.41,1044.14) 140.41,1068.14 194.25,1121.98 194.25,1306.14 ; v1(184.41,993.14) 184.41,1011.14 202.91,1029.64 220.69,1047.42 cw(c225.64,1042.47) 230.59,1047.42 234.12,1043.89 ccw(c239.07,1048.84) 244.02,1043.89 ccw(c239.07,1048.84) 244.02,1053.79 237.56,1060.25 cw(c242.51,1065.2) 237.56,1070.15 cw(c242.51,1065.2) 247.46,1070.15 253.92,1063.69 ccw(c258.87,1068.64) 263.82,1063.69 ccw(c258.87,1068.64) 263.82,1073.58 260.29,1077.12 cw(c265.24,1082.07) 260.29,1087.02 262.41,1089.14 270.41,1097.14 270.41,1178.14 253.31,1195.24 253.31,1306.14 ; v1(187.41,1083.14) 213.94,1109.67 213.94,1114.38 213.94,1127.14 cw(c220.94,1127.14) 220.94,1134.14 231.11,1134.14 ccw(c231.11,1141.14) 231.11,1148.14 220.94,1148.14 cw(c220.94,1155.14) 213.94,1155.14 213.94,1158.14 213.94,1306.14
  Top1 w10: -665.12,1245.12 -697.94,1245.12 -709.75,1256.93 ; -665.12,1256.93 -709.75,1256.93 ; -665.12,1434.09 -709.75,1434.09 ; -665.12,1445.91 -697.94,1445.91 -709.75,1434.09 ; -558.33,1375.04 -558.33,1394.72 -558.33,1414.41 v1(-558.33,1439.51) v1(-558.33,1464.01) v1(-558.33,1488.51) ; v1(-175.59,890.14) -175.59,897.14 v1(-160.59,912.14) ; -77.59,1037.85 -64.88,1037.85 -30.59,1072.14 -30.59,1092.14 -127.59,1189.14 -167.59,1189.14 ; -77.59,1297.54 -139.98,1297.54 -167.59,1325.14 ; -77.59,1557.22 -131.67,1557.22 -167.59,1593.14 ; -77.59,1816.91 -127.83,1816.91 -167.59,1777.14 ; -77.59,2076.59 -131.14,2076.59 -167.59,2040.14 -167.59,1777.14 ; v1(-59.59,1288.14) -5.59,1288.14 77.41,1205.14 109.41,1205.14 135.2,1230.93 135.2,1306.14 ; v1(17.41,942.14) 50.41,909.14 398.41,909.14 432.41,943.14 432.41,1025.14 505.41,1098.14 570.41,1098.14 581.41,1109.14 581.41,1135.14 554.41,1162.14 ; v1(394.41,1092.14) 404.41,1082.14 ; 404.41,1072.14 404.41,1082.14 ; 404.41,1102.14 404.41,1082.14 ; 409.41,1532.14 444.41,1532.14 444.41,1567.14 531.41,1567.14 555.94,1591.68 v1(555.94,1620.61) ; 444.41,1102.14 427.41,1119.14 427.41,1245.14 459.81,1277.54 v1(482.01,1277.54) ; 444.41,1607.14 444.41,1619.14 v1(456.41,1631.14) ; 482.01,1164.54 482.01,1202.2 ; 482.01,1316.2 v1(482.01,1277.54) ; 519.41,1162.14 v1(536.91,1162.14) 554.41,1162.14 ; 556.81,1202.2 556.81,1164.54 554.41,1162.14 ; -709.75,1256.93 v1(-723.33,1270.51) v1(-749.33,1270.51) v1(-778.33,1270.51) v1(-778.33,1420.51) v1(-749.33,1420.51) v1(-723.33,1420.51) -709.75,1434.09 ; -167.59,1189.14 -194.59,1216.14 -194.59,1298.14 -167.59,1325.14 ; -167.59,1189.14 -167.59,1072.14 -189.59,1050.14 -189.59,946.14 -132.59,889.14 398.21,889.14 446.41,937.34 446.41,1019.34 511.21,1084.14 579.41,1084.14 600.41,1105.14 600.41,1341.14 549.41,1392.14 549.41,1362.14 556.81,1354.74 556.81,1316.2 556.81,1278.54 533.41,1255.14 504.41,1255.14 v1(482.01,1277.54) ; -167.59,1325.14 -167.59,1452.14 -201.59,1486.14 -201.59,1559.14 -167.59,1593.14 ; -167.59,1593.14 -167.59,1777.14
  Top1 w15: v1(-105.59,1288.14) v1(-82.59,1288.14) v1(-59.59,1288.14)
  Bottom2 w4: v1(-100.59,1390.14) -122.59,1412.14 -122.59,1527.14 -102.75,1546.98 -76.59,1546.98 ; v1(-100.59,1430.14) -112.59,1442.14 -112.59,1517.7 -103,1527.3 -76.59,1527.3 ; -5.59,1027.14 3.62,1036.35 3.62,1074.46 15.41,1086.25 15.41,1177.14 24.94,1186.67 37.09,1186.67 45.94,1186.67 60.41,1201.14 60.41,1225.14 34.41,1251.14 34.41,1257.14 ; 37.09,1147.3 54.57,1147.3 69.41,1162.14 69.41,1257.14 ; v1(94.41,1275.14) 94.41,1298.46 120.1,1324.14 253.72,1324.14 273.07,1304.8 274.48,1303.38 ccw(c278.72,1307.63) 282.97,1303.38 285.34,1305.76 cw(c289.58,1301.52) 293.83,1305.76 cw(c289.58,1301.52) 293.83,1297.27 291.45,1294.9 ccw(c295.69,1290.66) 291.45,1286.41 302.07,1275.8 309.41,1268.46 309.41,1207.14 319.41,1197.14 360.61,1197.14 363.61,1194.14 ; v1(100.41,1251.14) 112.41,1263.14 112.41,1305.14 123.41,1316.14 250.41,1316.14 279.41,1287.14 v1(279.41,1267.14)
  Bottom2 w5: v1@-714.33,1335.83 v1(-714.33,1374.51)
  Bottom2 w6: -215.59,1172.14 -236.59,1172.14 -252.59,1156.14 -252.59,1062.14 -237.59,1047.14 -157.59,1047.14 -141.59,1031.14 -141.59,927.37 -101.36,887.14 405.69,887.14 465.44,946.89 465.44,1021.48 536.91,1092.94 v1(536.91,1162.14) ; -175.59,1137.14 -166.06,1127.61 -128.27,1127.61 ; -174.8,1206.35 -128.27,1206.35 -138.59,1216.68 v1(-138.59,1247.14) ; v1(-169.01,1288.72) -146.59,1311.14 -146.59,1469.14 v1(-176.59,1499.14) -176.59,1579.14 -102.59,1653.14 v1(-102.59,1738.14) -125.59,1761.14 -125.59,1798.14 -92.59,1831.14 -92.59,1963.56 v1(-126.88,1997.85) ; -128.27,1186.67 -161.06,1186.67 -175.59,1172.14 ; v1(-126.88,2037.22) -82.59,1992.93 -82.59,1799.14 v1(-103.59,1778.14) -78.59,1753.14 -78.59,1659.14 -154.59,1583.14 v1(-154.59,1525.14) -133.59,1504.14 -133.59,1274.14 v1(-130.59,1271.14) -154.59,1271.14 -195.59,1230.14 -195.59,1192.14 -175.59,1172.14 ; v1(-110.59,959.14) -70.59,959.14 v1(-35.59,924.14) -8.59,897.14 401.55,897.14 436.41,932 436.41,1019.14 493.41,1076.14 493.41,1179.14 459.41,1213.14 459.41,1470.05 470.5,1481.14 486.41,1481.14 504.41,1499.14 504.41,1620.61 ; 464.25,1550.84 451.11,1550.84 444.41,1544.14 444.41,1536.52 441.5,1533.61 441.5,1518.07 444.41,1515.17 444.41,1511.52 441.5,1508.61 441.5,1493.07 449.41,1485.17 449.41,1209 483.41,1175 483.41,1084.07 426.41,1027.07 426.41,936.14 397.41,907.14 9.41,907.14 -58.59,975.14 -88.59,975.14 v1(-111.59,998.14) -111.59,1072.06 -121.67,1082.14 -132.59,1082.14 -161.59,1111.14 -183.59,1111.14 -195.59,1123.14 -195.59,1152.14 -175.59,1172.14
  Bottom2 w10: v1(-778.33,1420.51) v1(-749.33,1420.51) v1(-723.33,1420.51) -577.33,1420.51 v1(-558.33,1439.51) v1(-558.33,1464.01) v1(-558.33,1488.51) ; -215.59,1172.14 -215.59,1207.14 ; -76.59,1487.93 -76.59,1507.61 ; v1(-59.59,1288.14) -53.59,1282.14 -50.59,1282.14 -50.59,1287.14 v1@-55.59,1292.14 ; -5.59,1027.14 -5.59,965.14 v1(17.41,942.14) ; 363.61,1044.14 406.41,1044.14 429.41,1067.14 454.41,1092.14 454.41,1117.14 429.41,1142.14 ; 363.61,1144.14 427.41,1144.14 ; 363.61,1294.14 422.41,1294.14 429.41,1287.14 ; v1(456.41,1631.14) 469.86,1631.14 480.39,1620.61 ; 528.43,1620.61 v1(555.94,1620.61) 580.41,1596.14 580.41,1533.14 573.11,1525.84 ; v1(536.91,1162.14) 573.11,1198.34 573.11,1525.84 ; 544.57,1500.84 544.57,1525.84 573.11,1525.84
  Bottom2 w15: v1(-105.59,1288.14) v1(-82.59,1288.14) v1(-59.59,1288.14) ; -76.59,1487.93 -76.59,1468.24 -76.59,1373.14 -50.59,1347.14 -50.59,1317.14
  Bottom2 w20: v1@-55.59,1292.14 -50.59,1297.14 -50.59,1317.14
  other v1: -84.59,935.14 94.41,952.14 244.41,972.14 64.41,977.14 94.41,1002.14 -30.59,1013.14 259.41,1017.14 304.41,1017.14 -29.59,1042.14 -128.59,1045.14 24.41,1047.14 289.41,1047.14 -143.59,1064.14 29.41,1072.14 -220.59,1077.14 304.72,1092.14 -225.59,1122.14 52.41,1128.14 304.41,1142.14 459.41,1142.14 454.41,1167.14 52.41,1168.14 304.41,1172.14 519.41,1197.14 284.41,1202.14 89.41,1227.14 519.41,1227.14 284.41,1232.14 -226.59,1243.14 -226.59,1276.14 69.41,1288.14 519.41,1297.14 -754.33,1300.51 29.41,1317.14 54.41,1317.14 389.41,1332.14 -100.59,1337.14 -77.59,1336.91 389.41,1362.14 489.41,1367.14 -225.59,1372.14 -754.33,1390.51 389.41,1392.14 489.41,1407.14 -225.59,1412.14 389.41,1422.14 -225.59,1452.14 389.41,1452.14 544.41,1452.14 -225.59,1492.14 -225.59,1532.14 -225.59,1572.14 -225.59,1612.14 404.41,1617.14 -60.59,1637.14 -225.59,1652.14 404.41,1652.14 -130.59,1672.14 -225.59,1692.14 -130.59,1707.14 -225.59,1732.14 -225.59,1772.14 -225.59,1812.14 -225.59,1852.14 -130.59,1887.14 -225.59,1892.14 -130.59,1917.14 -225.59,1932.14 -130.59,1947.14 -225.59,1972.14 -225.59,2012.14 -225.59,2052.14 -225.59,2092.14 -225.59,2132.14

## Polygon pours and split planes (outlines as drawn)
no net on Top1 "NONET_L01_P010" (solid, remove dead copper, pour order 10): -914.33,905.51 -914.33,1785.51 -354.33,1785.51 -354.33,905.51
no net on Top1 "NONET_L01_P008" (solid, remove dead copper, pour order 8): 674.41,2237.14 674.41,837.14 -275.59,837.14 -275.59,2237.14
GND on Top1 "NONET_L01_P-001" (solid, remove dead copper, pour order 0): -800,850 800,850 800,-800 -800,-800
no net on Bottom2 "NONET_L02_P011" (solid, remove dead copper, pour order 11): -914.33,905.51 -914.33,1785.51 -354.33,1785.51 -354.33,905.51
no net on Bottom2 "NONET_L02_P009" (solid, remove dead copper, pour order 9): 674.41,2237.14 674.41,837.14 -275.59,837.14 -275.59,2237.14
GND on Bottom2 "NONET_L01_P-001" (solid, remove dead copper, pour order 1): -800,850 800,850 800,-800 -800,-800

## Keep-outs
Keep-Out Layer:
  lines w5: -275.59,1100.59 -275.59,887.54 ccw(c-255.91,887.54) -255.91,867.85 ; -275.59,1591.41 -275.59,2186.75 cw(c-255.91,2186.75) -255.91,2206.43 -78.74,2206.43 cw(c-78.74,2167.06) -39.37,2167.06 -39.37,1379.66 ccw(c0,1379.66) 0,1340.29 314.96,1340.29 ccw(c314.96,1379.66) 354.33,1379.66 354.33,1891.47 cw(c433.07,1891.47) 433.07,1970.21 590.55,1970.21 cw(c590.55,1891.47) 669.29,1891.47 669.29,946.59 cw(c590.55,946.59) 590.55,867.85 256.85,867.85
  lines w10: -327.58,654.33 -292.13,716.15 -256.03,779.09 -256.03,867.72 ; -327.21,653.58 ccw(c0,-10) 326.51,653.93 ; -275.59,1100.59 -278.66,1103.66 -456.85,1103.66 ccw(c-456.85,1083.98) -476.54,1083.98 -476.54,1045.51 cw(c-614.33,1045.51) -752.13,1045.51 -752.13,1089.61 ccw(c-771.81,1089.61) -771.81,1109.29 -875.58,1109.29 cw(c-875.58,1148.66) -914.95,1148.66 -914.95,1542.36 cw(c-875.58,1542.36) -875.58,1581.73 -771.81,1581.73 ccw(c-771.81,1601.42) -752.13,1601.42 -752.13,1645.51 cw(c-614.33,1645.51) -476.54,1645.51 -476.54,1607.05 ccw(c-456.85,1607.05) -456.85,1587.36 -394.32,1587.36 -279.64,1587.36 -275.59,1591.41 ; 256.85,867.85 254.64,865.64 254.64,779.01 290.88,716.22 326.65,654.22

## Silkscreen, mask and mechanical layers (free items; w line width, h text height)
Top Overlay:
  drawing of 387 lines, arcs and shapes, not listed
